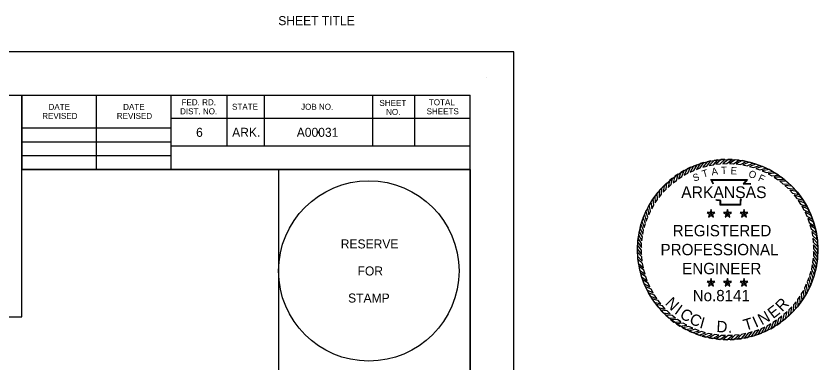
# Model space of a CAD drawing. Extents: x 0 to 19, y -0.6 to 11.2.
# Drawn here: x 13.69 to 19.02, y 8.93 to 11.24 of the extents above; entities that cross this region are included whole.
import ezdxf

# ---------------------------------------------------------------- set-up
doc = ezdxf.new("R2010")
doc.units = 0
for name, color, linetype in [('G-ANNO-STMP', 7, 'Continuous'), ('G-ANNO-TEXT', 7, 'Continuous'), ('G-Border-Paper', 7, 'Continuous'), ('G-Border-Sheet', 7, 'Continuous'), ('G-No Plot-Anchor', 7, 'Continuous'), ('G-No Plot-Border-1', 7, 'Continuous'), ('G-No Plot-Border-2', 7, 'Continuous'), ('G-No Plot-Stamp-1', 7, 'Continuous'), ('G-No Plot-Stamp-2', 7, 'Continuous'), ('G-Table-Major', 7, 'Continuous'), ('G-Table-Minor', 7, 'Continuous')]:
    doc.layers.add(name, color=color, linetype=linetype)

msp = doc.modelspace()

# ---------------------------------------------------------------- linework, layer by layer
at = {"layer": 'G-ANNO-STMP'}
for points in [[(18.2203, 10.2486), (18.1962, 10.2394), (18.1735, 10.1994), (18.1989, 10.2109)], [(18.2652, 10.2627), (18.2405, 10.2554), (18.2148, 10.2173), (18.241, 10.2268)], [(18.3112, 10.2732), (18.2859, 10.2679), (18.2573, 10.2319), (18.2842, 10.2393)], [(18.3578, 10.2801), (18.3322, 10.2768), (18.3008, 10.2431), (18.3282, 10.2484)], [(18.4048, 10.2833), (18.379, 10.282), (18.3451, 10.2509), (18.3728, 10.254)], [(18.4519, 10.2828), (18.4261, 10.2835), (18.3899, 10.2552), (18.4177, 10.2561)], [(18.4988, 10.2786), (18.4732, 10.2813), (18.4348, 10.256), (18.4627, 10.2546)], [(18.5453, 10.2707), (18.5199, 10.2755), (18.4797, 10.2532), (18.5073, 10.2497)], [(18.591, 10.2592), (18.5661, 10.266), (18.5242, 10.2469), (18.5515, 10.2412)], [(18.6356, 10.2442), (18.6113, 10.2529), (18.5681, 10.2371), (18.5949, 10.2294)], [(18.0939, 10.1859), (18.0726, 10.1714), (18.06, 10.1272), (18.082, 10.1443)], [(18.1344, 10.2101), (18.112, 10.1973), (18.0959, 10.1542), (18.1192, 10.1695)], [(18.1766, 10.2311), (18.1533, 10.22), (18.1338, 10.1783), (18.1582, 10.1918)], [(18.6789, 10.2257), (18.6554, 10.2362), (18.6111, 10.224), (18.6372, 10.2141)], [(18.7207, 10.2039), (18.698, 10.2162), (18.6529, 10.2074), (18.6781, 10.1956)], [(18.7606, 10.1788), (18.739, 10.1929), (18.6933, 10.1877), (18.7175, 10.1739)], [(18.0555, 10.1587), (18.0354, 10.1425), (18.0263, 10.0974), (18.0469, 10.1162)], [(18.7984, 10.1507), (18.778, 10.1665), (18.732, 10.1649), (18.7551, 10.1492)], [(18.8339, 10.1197), (18.8148, 10.137), (18.7688, 10.1391), (18.7906, 10.1216)], [(17.9857, 10.0955), (17.9684, 10.0764), (17.9664, 10.0304), (17.9838, 10.0522)], [(18.0194, 10.1284), (18.0006, 10.1107), (17.995, 10.0651), (18.0141, 10.0854)], [(18.8669, 10.0861), (18.8491, 10.1048), (18.8035, 10.1104), (18.8238, 10.0914)], [(18.8971, 10.0499), (18.8809, 10.07), (18.8358, 10.0792), (18.8546, 10.0586)], [(17.9547, 10.06), (17.939, 10.0396), (17.9406, 9.9936), (17.9562, 10.0167)], [(18.9244, 10.0115), (18.9098, 10.0328), (18.8656, 10.0455), (18.8827, 10.0235)], [(17.9016, 9.9823), (17.8892, 9.9596), (17.898, 9.9145), (17.9099, 9.9397)], [(17.9266, 10.0222), (17.9125, 10.0006), (17.9177, 9.9549), (17.9315, 9.9791)], [(18.9485, 9.9711), (18.9357, 9.9935), (18.8926, 10.0096), (18.9079, 9.9863)], [(17.8798, 9.9405), (17.8692, 9.917), (17.8815, 9.8727), (17.8913, 9.8987)], [(18.3122, 9.9224), (18.3061, 9.9309), (18.2861, 9.9309), (18.3023, 9.9192)], [(18.3122, 9.9224), (18.3023, 9.9192), (18.2961, 9.9003), (18.3122, 9.912)], [(18.3122, 9.9224), (18.3184, 9.9309), (18.3122, 9.9499), (18.3061, 9.9309)], [(18.3122, 9.9224), (18.3222, 9.9192), (18.3383, 9.9309), (18.3184, 9.9309)], [(18.3122, 9.9224), (18.3122, 9.912), (18.3283, 9.9003), (18.3222, 9.9192)], [(18.4219, 9.9224), (18.4158, 9.9309), (18.3958, 9.9309), (18.412, 9.9192)], [(18.4219, 9.9224), (18.412, 9.9192), (18.4058, 9.9003), (18.4219, 9.912)], [(18.4219, 9.9224), (18.4281, 9.9309), (18.4219, 9.9499), (18.4158, 9.9309)], [(18.4219, 9.9224), (18.4319, 9.9192), (18.448, 9.9309), (18.4281, 9.9309)], [(18.4219, 9.9224), (18.4219, 9.912), (18.4381, 9.9003), (18.4319, 9.9192)], [(18.5317, 9.9224), (18.5255, 9.9309), (18.5056, 9.9309), (18.5217, 9.9192)], [(18.5317, 9.9224), (18.5217, 9.9192), (18.5155, 9.9003), (18.5317, 9.912)], [(18.5317, 9.9224), (18.5378, 9.9309), (18.5317, 9.9499), (18.5255, 9.9309)], [(18.5317, 9.9224), (18.5416, 9.9192), (18.5577, 9.9309), (18.5378, 9.9309)], [(18.5317, 9.9224), (18.5317, 9.912), (18.5478, 9.9003), (18.5416, 9.9192)], [(18.9695, 9.9289), (18.9584, 9.9522), (18.9167, 9.9716), (18.9302, 9.9472)], [(18.987, 9.8852), (18.9779, 9.9093), (18.9378, 9.9319), (18.9493, 9.9065)], [(17.8613, 9.8972), (17.8526, 9.8729), (17.8683, 9.8297), (17.8761, 9.8564)], [(19.0011, 9.8402), (18.9939, 9.865), (18.9557, 9.8907), (18.9652, 9.8645)], [(17.8462, 9.8525), (17.8395, 9.8276), (17.8586, 9.7858), (17.8642, 9.8131)], [(19.0116, 9.7943), (19.0063, 9.8195), (18.9703, 9.8482), (18.9777, 9.8213)], [(17.8269, 9.7604), (17.8241, 9.7347), (17.8495, 9.6964), (17.8508, 9.7242)], [(17.8347, 9.8069), (17.83, 9.7815), (17.8523, 9.7413), (17.8558, 9.7689)], [(19.0185, 9.7477), (19.0152, 9.7733), (18.9816, 9.8046), (18.9868, 9.7772)], [(19.0217, 9.7007), (19.0204, 9.7264), (18.9893, 9.7603), (18.9924, 9.7326)], [(17.8227, 9.7135), (17.8219, 9.6877), (17.8503, 9.6514), (17.8494, 9.6793)], [(19.0212, 9.6536), (19.0219, 9.6793), (18.9936, 9.7156), (18.9945, 9.6877)], [(17.8222, 9.6664), (17.8235, 9.6406), (17.8545, 9.6067), (17.8515, 9.6344)], [(19.017, 9.6066), (19.0198, 9.6323), (18.9944, 9.6706), (18.9931, 9.6428)], [(17.8254, 9.6194), (17.8287, 9.5938), (17.8623, 9.5624), (17.8571, 9.5898)], [(19.0091, 9.5602), (19.0139, 9.5855), (18.9916, 9.6258), (18.9881, 9.5981)], [(17.8322, 9.5728), (17.8375, 9.5475), (17.8735, 9.5189), (17.8662, 9.5458)], [(18.9976, 9.5145), (19.0044, 9.5394), (18.9853, 9.5812), (18.9797, 9.5539)], [(17.8427, 9.5268), (17.85, 9.5021), (17.8881, 9.4764), (17.8787, 9.5026)], [(18.9641, 9.4265), (18.9747, 9.4501), (18.9624, 9.4944), (18.9525, 9.4683)], [(18.9826, 9.4698), (18.9913, 9.4941), (18.9755, 9.5374), (18.9678, 9.5106)], [(17.8568, 9.4819), (17.866, 9.4578), (17.906, 9.4351), (17.8946, 9.4605)], [(18.3122, 9.463), (18.3061, 9.4715), (18.2861, 9.4715), (18.3023, 9.4598)], [(18.3122, 9.463), (18.3023, 9.4598), (18.2961, 9.4408), (18.3122, 9.4525)], [(18.3122, 9.463), (18.3184, 9.4715), (18.3122, 9.4904), (18.3061, 9.4715)], [(18.3122, 9.463), (18.3222, 9.4598), (18.3383, 9.4715), (18.3184, 9.4715)], [(18.3122, 9.463), (18.3122, 9.4525), (18.3283, 9.4408), (18.3222, 9.4598)], [(18.4219, 9.463), (18.4158, 9.4715), (18.3958, 9.4715), (18.412, 9.4598)], [(18.4219, 9.463), (18.412, 9.4598), (18.4058, 9.4408), (18.4219, 9.4525)], [(18.4219, 9.463), (18.4281, 9.4715), (18.4219, 9.4904), (18.4158, 9.4715)], [(18.4219, 9.463), (18.4319, 9.4598), (18.448, 9.4715), (18.4281, 9.4715)], [(18.4219, 9.463), (18.4219, 9.4525), (18.4381, 9.4408), (18.4319, 9.4598)], [(18.5317, 9.463), (18.5255, 9.4715), (18.5056, 9.4715), (18.5217, 9.4598)], [(18.5317, 9.463), (18.5217, 9.4598), (18.5155, 9.4408), (18.5317, 9.4525)], [(18.5317, 9.463), (18.5378, 9.4715), (18.5317, 9.4904), (18.5255, 9.4715)], [(18.5317, 9.463), (18.5416, 9.4598), (18.5577, 9.4715), (18.5378, 9.4715)], [(18.5317, 9.463), (18.5317, 9.4525), (18.5478, 9.4408), (18.5416, 9.4598)], [(18.9423, 9.3848), (18.9546, 9.4074), (18.9459, 9.4526), (18.934, 9.4273)], [(17.8744, 9.4382), (17.8854, 9.4148), (17.9271, 9.3954), (17.9137, 9.4198)], [(17.8953, 9.3959), (17.9082, 9.3736), (17.9513, 9.3575), (17.9359, 9.3808)], [(18.9172, 9.3449), (18.9313, 9.3665), (18.9261, 9.4122), (18.9123, 9.3879)], [(17.9195, 9.3555), (17.9341, 9.3342), (17.9783, 9.3215), (17.9612, 9.3436)], [(18.8582, 9.2715), (18.8755, 9.2907), (18.8775, 9.3366), (18.8601, 9.3149)], [(18.8891, 9.307), (18.9049, 9.3275), (18.9033, 9.3734), (18.8876, 9.3504)], [(17.9468, 9.3171), (17.963, 9.297), (18.0081, 9.2879), (17.9893, 9.3085)], [(17.977, 9.281), (17.9947, 9.2622), (18.0404, 9.2566), (18.02, 9.2757)], [(18.8245, 9.2386), (18.8432, 9.2563), (18.8489, 9.302), (18.8298, 9.2816)], [(18.01, 9.2473), (18.0291, 9.23), (18.075, 9.228), (18.0533, 9.2454)], [(18.7499, 9.1811), (18.7712, 9.1957), (18.7839, 9.2399), (18.7619, 9.2228)], [(18.7883, 9.2084), (18.8084, 9.2246), (18.8176, 9.2696), (18.797, 9.2509)], [(18.0455, 9.2163), (18.0659, 9.2006), (18.1119, 9.2022), (18.0888, 9.2178)], [(18.0833, 9.1882), (18.1049, 9.1741), (18.1506, 9.1793), (18.1264, 9.1931)], [(18.6673, 9.136), (18.6906, 9.147), (18.71, 9.1887), (18.6856, 9.1753)], [(18.7095, 9.1569), (18.7319, 9.1698), (18.748, 9.2128), (18.7247, 9.1975)], [(18.1232, 9.1632), (18.1458, 9.1508), (18.191, 9.1596), (18.1657, 9.1714)], [(18.1649, 9.1413), (18.1885, 9.1308), (18.2328, 9.1431), (18.2067, 9.1529)], [(18.2083, 9.1228), (18.2326, 9.1142), (18.2758, 9.1299), (18.249, 9.1377)], [(18.2529, 9.1078), (18.2778, 9.1011), (18.3197, 9.1201), (18.2924, 9.1258)], [(18.4861, 9.0869), (18.5117, 9.0903), (18.543, 9.1239), (18.5157, 9.1187)], [(18.5327, 9.0938), (18.5579, 9.0991), (18.5866, 9.1351), (18.5597, 9.1278)], [(18.5786, 9.1043), (18.6034, 9.1116), (18.6291, 9.1497), (18.6029, 9.1403)], [(18.6236, 9.1184), (18.6477, 9.1276), (18.6703, 9.1676), (18.6449, 9.1561)], [(18.2986, 9.0963), (18.324, 9.0916), (18.3642, 9.1139), (18.3365, 9.1173)], [(18.345, 9.0885), (18.3707, 9.0857), (18.4091, 9.1111), (18.3812, 9.1124)], [(18.392, 9.0843), (18.4178, 9.0835), (18.454, 9.1118), (18.4261, 9.1109)], [(18.4391, 9.0837), (18.4649, 9.085), (18.4988, 9.1161), (18.4711, 9.113)]]:
    msp.add_lwpolyline(points, close=True, dxfattribs=at)
for points in [[(18.3258, 10.119), (18.3118, 10.1493), (18.5538, 10.1494), (18.5336, 10.124), (18.5501, 10.1242), (18.5638, 10.1244), (18.5775, 10.1229)], [(18.3293, 10.1206), (18.3178, 10.1455), (18.5459, 10.1456), (18.5256, 10.1201), (18.5501, 10.1204), (18.5636, 10.1206), (18.5771, 10.1191)], [(18.5157, 10.0176), (18.5116, 10.0142), (18.5102, 10.0092), (18.5088, 9.9966), (18.5088, 9.9799), (18.3737, 9.9799), (18.3737, 10.0025), (18.3737, 10.0075), (18.3683, 10.0092), (18.349, 10.0092), (18.3456, 10.0144)], [(18.5133, 10.0205), (18.5082, 10.0164), (18.5064, 10.0099), (18.505, 9.9969), (18.505, 9.9838), (18.3776, 9.9838), (18.3776, 10.0025), (18.3776, 10.0104), (18.3688, 10.013), (18.3511, 10.013), (18.3488, 10.0165)]]:
    msp.add_lwpolyline(points, dxfattribs=at)
at = {"layer": 'G-ANNO-TEXT'}
msp.add_line((16.821, 10.8269), (16.821, 10.8269), dxfattribs=at)
at = {"layer": 'G-Border-Paper'}
msp.add_lwpolyline([(17, 11), (0, 11), (0, 0), (17, 0)], close=True, dxfattribs=at)
at = {"layer": 'G-Border-Sheet'}
for p in [(0.758, 10.7116), (16.7116, 0.2884)]:
    msp.add_line(p, (16.7116, 10.7116), dxfattribs=at)
at = {"layer": 'G-No Plot-Anchor'}
msp.add_circle((15.7013, 10.4639), 0.005, dxfattribs=at)
at = {"layer": 'G-No Plot-Border-1'}
msp.add_lwpolyline([(0.758, 5.4354), (0.758, 10.7116), (13.7281, 10.7116), (13.7281, 10.2161), (14.7206, 10.2161), (14.8974, 10.2161), (15.4366, 10.2161), (15.4366, 8.7411), (16.7116, 8.7411), (16.7116, 5.4354)], close=True, dxfattribs=at)
at = {"layer": 'G-No Plot-Border-2'}
msp.add_lwpolyline([(0.758, 5.4354), (0.758, 10.7116), (12.3781, 10.7116), (12.3781, 9.2366), (13.7281, 9.2366), (13.7281, 10.2161), (14.7206, 10.2161), (14.8974, 10.2161), (16.7116, 10.2161), (16.7116, 5.4354)], close=True, dxfattribs=at)
at = {"layer": 'G-No Plot-Stamp-1'}
for centre in [(18.4233, 9.6835), (16.0366, 9.5411)]:
    msp.add_circle(centre, 0.6, dxfattribs=at)
at = {"layer": 'G-No Plot-Stamp-2'}
msp.add_circle((18.4233, 9.6835), 0.6, dxfattribs=at)
at = {"layer": 'G-Table-Major'}
for p, q in [((13.7281, 10.2168), (13.7281, 10.7116)), ((14.7206, 10.7116), (14.7206, 10.2161)), ((13.7281, 10.4946), (14.7206, 10.4946)), ((16.7116, 10.2161), (13.7281, 10.2161))]:
    msp.add_line(p, q, dxfattribs=at)
at = {"layer": 'G-Table-Minor'}
for p, q in [((14.2256, 10.2165), (14.2256, 10.7116)), ((15.0926, 10.7116), (15.0926, 10.3716)), ((15.3411, 10.7116), (15.3411, 10.3716)), ((16.0616, 10.7116), (16.0616, 10.3716)), ((16.3396, 10.7116), (16.3396, 10.3716)), ((16.7116, 10.5656), (16.7116, 10.5656)), ((16.7116, 10.5561), (14.7206, 10.5561)), ((13.7281, 10.4011), (14.7206, 10.4011)), ((16.7116, 10.3716), (14.7206, 10.3716)), ((13.7281, 10.3096), (14.7206, 10.3096))]:
    msp.add_line(p, q, dxfattribs=at)

# ---------------------------------------------------------------- texts
at = {"layer": 'G-ANNO-STMP'}
for s, height, rotation, p in [('S', 0.0477, 19.7726, (18.1998, 10.1349)), ('T', 0.0477, 16.9015, (18.2605, 10.1621)), ('A', 0.0477, 8.6788, (18.3184, 10.1773)), ('T', 0.0477, 1.4789, (18.3801, 10.1868)), ('E', 0.0477, 356.672, (18.4412, 10.1853)), ('O', 0.0477, 341.2218, (18.5571, 10.1689)), ('F', 0.0477, 335.3628, (18.6214, 10.1438)), ('N', 0.0754, 315.2676, (18.0028, 9.3216)), ('R', 0.0754, 45.478, (18.7853, 9.2657)), ('I', 0.0754, 324.2141, (18.0641, 9.2609)), ('C', 0.0754, 328.6873, (18.0982, 9.2342)), ('E', 0.0754, 37.6498, (18.725, 9.2201)), ('C', 0.0754, 336.5155, (18.1624, 9.1943)), ('I', 0.0754, 344.3437, (18.2314, 9.1635)), ('T', 0.0754, 16.7747, (18.54, 9.1425)), ('I', 0.0754, 24.2301, (18.6092, 9.1624)), ('N', 0.0754, 28.7033, (18.6493, 9.1786)), ('D', 0.0754, 356.6451, (18.3466, 9.1349)), ('.', 0.0754, 4.846, (18.4256, 9.1298))]:
    msp.add_text(s, height=height, rotation=rotation, dxfattribs=at).set_placement(p)
for s, height, p in [('ARKANSAS', 0.07791, (18.114, 10.0263)), ('REGISTERED', 0.07543, (18.0574, 9.7719)), ('PROFESSIONAL', 0.07543, (17.9765, 9.6458)), ('ENGINEER', 0.07543, (18.1202, 9.5197)), ('No.8141', 0.07513, (18.1905, 9.3398))]:
    msp.add_text(s, height=height, dxfattribs=at).set_placement(p)
at = {"layer": 'G-ANNO-TEXT'}
for s, height, p in [('SHEET TITLE', 0.06, (15.4345, 11.1771)), ('FED. RD.', 0.04, (14.7913, 10.6439)), ('SHEET', 0.04, (16.1072, 10.6396)), ('TOTAL', 0.04, (16.4361, 10.6439)), ('DATE', 0.04, (13.9066, 10.6131)), ('DATE', 0.04, (14.4029, 10.6131)), ('DIST. NO.', 0.04, (14.7816, 10.5839)), ('STATE', 0.04, (15.1271, 10.6139)), ('JOB NO.', 0.04, (15.5861, 10.6139)), ('NO.', 0.04, (16.1515, 10.5796)), ('SHEETS', 0.04, (16.421, 10.5839)), ('REVISED', 0.04, (13.8646, 10.5531)), ('REVISED', 0.04, (14.3608, 10.5531)), ('6', 0.06, (14.8879, 10.4339)), ('ARK.', 0.06, (15.1276, 10.4339)), ('A00031', 0.06, (15.5573, 10.4339))]:
    msp.add_text(s, height=height, dxfattribs=at).set_placement(p)
at = {"layer": 'G-No Plot-Stamp-1'}
for s, p in [('RESERVE', (15.85, 9.6911)), ('FOR ', (15.9617, 9.5111)), ('STAMP', (15.8989, 9.3311))]:
    msp.add_text(s, height=0.06, dxfattribs=at).set_placement(p)

doc.saveas('drawing.dxf')
